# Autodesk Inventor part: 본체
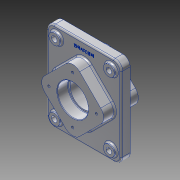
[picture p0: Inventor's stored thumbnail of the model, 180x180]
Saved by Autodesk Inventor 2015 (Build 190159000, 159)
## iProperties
Created: 2026-07
Part Number: 본체
Material: 알루미늄 6061
Document SubType Name: Modeling
Designer: USER
Density: 2.7 g/cm^3
Appearance: 알루미늄 - 평지
Mass: 2132.41 g
Surface Area: 955.114 cm^2
Volume: 789.782 cm^3
Author: USER
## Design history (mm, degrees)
sketch "스케치1"
  geometry: L1 (75, -90)-(-75, -90); L2 (-75, -90)-(-75, 90); L3 (-75, 90)-(75, 90); L4 (75, 90)-(75, -90); L5 (75, -90)-(-75, 90); L6 (-75, -90)-(75, 90); 1 further point
  constraints: 12 end point, 2 midpoint, 2 parallel, 1 horizontal, 1 perpendicular
  dimensions: "d0" = 150 distance of L2.end L3.end; "d1" = 180 distance of L1.end L2.end
extrude "돌출1" new body sketch "스케치1" distance "d2" = 18; taper "d3" = 0 deg
fillet "모깎기1" dims "d4" = 15
sketch "스케치5"
  geometry: L1 (0, 70.711)-(70.711, 0); L2 (70.711, 0)-(0, -70.711); L3 (0, -70.711)-(-70.711, 0); L4 (-70.711, 0)-(0, 70.711); 2 further points
  constraints: 8 end point, 1 coincident, 1 vertical alignment, 9 other
  dimensions: "d5" = 100 distance of L1.start L1.end
extrude "돌출2" join sketch "스케치5" distance "d6" = 23; taper "d7" = 0 deg
fillet "모깎기2" dims "d10" = 20
sketch "스케치8"
  geometry: L1 (0, -70.711)-(-70.711, 0); L2 (-70.711, 0)-(0, 70.711); L3 (0, 70.711)-(70.711, 0); L4 (70.711, 0)-(0, -70.711); 2 further points
  constraints: 8 end point, 1 coincident, 1 vertical alignment, 9 other
  dimensions: "d12" = 100 distance of L1.start L1.end
extrude "돌출3" join sketch "스케치8" distance "d13" = 29; taper "d14" = 0 deg
fillet "모깎기3" dims "d15" = 20
sketch "스케치10"
  geometry: L1 (-75, -75)-(-75, 75) reference; C1 r 11 at (-55, 70); 1 further point
  constraints: 1 centre point
  dimensions: "d16" = 22 diameter of C1; "d17" = 20 distance from line of C1.centre L1
extrude "돌출4" join sketch "스케치10" distance "d18" = 5; taper "d19" = 0 deg
hole "구멍1" diameter "d22" = 11; stored, may be unused: countersink angle "d26" = 90 deg, drill point angle "d28" = 0 deg; dims "d20" = 10, "d21" = 10, "d23" = 6, "d24" = 4, "d25" = 2, "d27" = 8.8
sketch "스케치12"
  geometry: L1 (60, 90)-(-60, 90) reference; 3 further points
  constraints: 1 midpoint, 1 vertical alignment, 1 other
  dimensions: "d37" = 15 distance from line of point (0, 75) L1
feature "엠보싱1" sketch "스케치12" dims "d0" = 150, "d1" = 180, "d10" = 20, "d38" = 0.5, "d39" = 0
sketch "스케치13"
  geometry: C1 r 31 at (0, 0); 1 further point
  constraints: 1 centre point, 1 coincident
  dimensions: "d40" = 62 diameter of C1
extrude "돌출5" cut sketch "스케치13" distance "d41" = 22; taper "d42" = 0 deg
hole "구멍2" diameter "d45" = 54; stored, may be unused: countersink angle "d49" = 90 deg, drill point angle "d51" = 0 deg; dims "d43" = 10, "d44" = 10, "d46" = 6, "d47" = 4, "d48" = 2, "d50" = 8.8
sketch "스케치14"
  geometry: C1 r 31 at (0, 0); 1 further point
  constraints: 1 centre point, 1 coincident
  dimensions: "d52" = 62 diameter of C1
extrude "돌출6" cut sketch "스케치14" distance "d53" = 22; taper "d54" = 0 deg
sketch "스케치15"
  geometry: L1 (0, 0)-(0, 48)
  constraints: 2 end point, 1 vertical
  dimensions: "d55" = 48 distance of L1.start L1.end
hole "구멍3" sketch "스케치15" at (0, 48) diameter "d56" = 4.917; stored, may be unused: countersink angle "d60" = 90 deg, drill point angle "d62" = 118 deg; dims "d57" = 10, "d58" = 4, "d59" = 2, "d61" = 13
sketch "스케치16"
  geometry: L1 (0, 0)-(0, -48)
  constraints: 2 end point, 1 vertical
  dimensions: "d66" = 48 distance of L1.start L1.end
hole "구멍4" sketch "스케치16" at (0, -48) diameter "d67" = 4.917; stored, may be unused: countersink angle "d71" = 90 deg, drill point angle "d73" = 118 deg; dims "d68" = 10, "d69" = 4, "d70" = 2, "d72" = 13
fillet "모깎기4" dims "d77" = 3
fillet "모깎기5" dims "d78" = 1
chamfer "모따기1" distance "d79" = 1; stored, may be unused: second distance "d80" = 2, angle "d81" = 45 deg
node "솔리드1"
pattern_linear "직사각형 패턴1"
pattern_circular "원형 패턴1" dims angle "d64" = 360 deg
pattern_circular "원형 패턴2" dims angle "d75" = 360 deg
